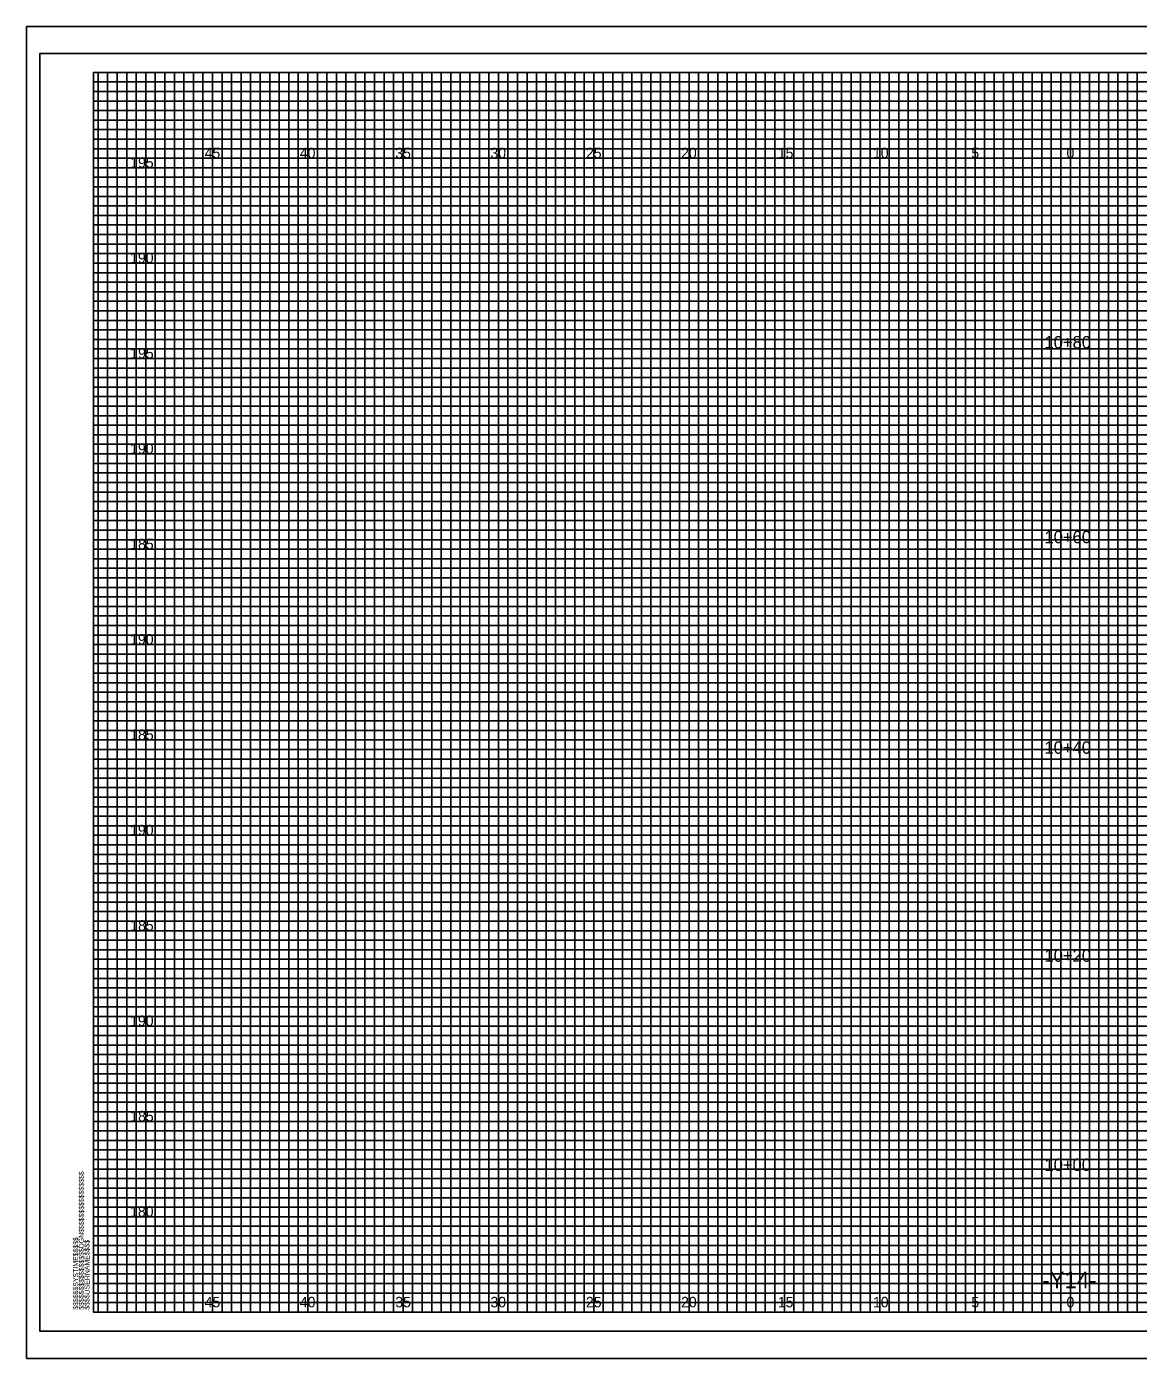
# Model space of a CAD drawing. Extents: x -4 to 103, y -2 to 138.
# Drawn here: x -3.5 to 54.8, y -2.4 to 67.4 of the extents above; entities that cross this region are included whole.
import ezdxf

# ---------------------------------------------------------------- set-up
doc = ezdxf.new("R2010")
doc.units = 0
for name, color, linetype in [('Old_Level_10', 7, 'Continuous'), ('Old_Level_16', 7, 'Continuous'), ('Old_Level_3', 7, 'Continuous'), ('Old_Level_5', 7, 'Continuous'), ('Old_Level_8', 7, 'Continuous'), ('Prop Dimension', 7, 'Continuous'), ('Prop XS Finish Grade Earthwork', 7, 'Continuous'), ('Prop XS Pvmt Edge Slope', 7, 'Continuous'), ('Prop XS SE Text', 7, 'Continuous'), ('Prop XS Subgrade Earthwork', 7, 'Continuous'), ('Prop XSC Text', 7, 'Continuous')]:
    doc.layers.add(name, color=color, linetype=linetype)

msp = doc.modelspace()

# ---------------------------------------------------------------- linework, layer by layer
at = {"layer": 'Old_Level_10'}
for p, q in [((1.25, 0), (1.25, 65)), ((3.75, 0), (3.75, 65)), ((6.25, 0), (6.25, 65)), ((8.75, 0), (8.75, 65)), ((11.25, 0), (11.25, 65)), ((13.75, 0), (13.75, 65)), ((16.25, 0), (16.25, 65)), ((18.75, 0), (18.75, 65)), ((21.25, 0), (21.25, 65)), ((23.75, 0), (23.75, 65)), ((26.25, 0), (26.25, 65)), ((28.75, 0), (28.75, 65)), ((31.25, 0), (31.25, 65)), ((33.75, 0), (33.75, 65)), ((36.25, 0), (36.25, 65)), ((38.75, 0), (38.75, 65)), ((41.25, 0), (41.25, 65)), ((43.75, 0), (43.75, 65)), ((46.25, 0), (46.25, 65)), ((48.75, 0), (48.75, 65)), ((51.25, 0), (51.25, 65)), ((53.75, 0), (53.75, 65)), ((0, 62.5), (74.25, 62.5)), ((0, 60), (102.5, 60)), ((0, 57.5), (102.5, 57.5)), ((0, 55), (102.5, 55)), ((0, 52.5), (102.5, 52.5)), ((0, 50), (102.5, 50)), ((0, 47.5), (102.5, 47.5)), ((0, 45), (102.5, 45)), ((0, 42.5), (102.5, 42.5)), ((0, 40), (102.5, 40)), ((0, 37.5), (102.5, 37.5)), ((0, 35), (102.5, 35)), ((0, 32.5), (102.5, 32.5)), ((0, 30), (102.5, 30)), ((0, 27.5), (102.5, 27.5)), ((0, 25), (102.5, 25)), ((0, 22.5), (102.5, 22.5)), ((0, 20), (102.5, 20)), ((0, 17.5), (102.5, 17.5)), ((0, 15), (102.5, 15)), ((0, 12.5), (102.5, 12.5)), ((0, 10), (102.5, 10)), ((0, 7.5), (102.5, 7.5)), ((0, 5), (102.5, 5)), ((0, 2.5), (102.5, 2.5))]:
    msp.add_line(p, q, dxfattribs=at)
at = {"layer": 'Old_Level_3'}
for p, q in [((-3.5, 67.4), (103.4, 67.4)), ((-3.5, 67.4), (-3.5, -2.425)), ((-3.5, -2.425), (103.4, -2.425))]:
    msp.add_line(p, q, dxfattribs=at)
at = {"layer": 'Old_Level_5'}
msp.add_lwpolyline([(103.4, 67.4), (-3.5, 67.4), (-3.5, -2.425), (103.4, -2.425)], close=True, dxfattribs=at)
at = {"layer": 'Old_Level_8'}
for points in [[(1.25, 0), (1.25, 65), (3.75, 65), (3.75, 0), (6.25, 0), (6.25, 65), (8.75, 65), (8.75, 0), (11.25, 0), (11.25, 65), (13.75, 65), (13.75, 0), (16.25, 0), (16.25, 65), (18.75, 65), (18.75, 0), (21.25, 0), (21.25, 65), (23.75, 65), (23.75, 0), (26.25, 0), (26.25, 65), (28.75, 65), (28.75, 0), (31.25, 0), (31.25, 65), (33.75, 65), (33.75, 0), (36.25, 0), (36.25, 65), (38.75, 65), (38.75, 0), (41.25, 0), (41.25, 65), (43.75, 65), (43.75, 0), (46.25, 0), (46.25, 65), (48.75, 65), (48.75, 0), (51.25, 0), (51.25, 65), (53.75, 65), (53.75, 0)], [(102.5, 60), (0, 60), (0, 62.5), (74.25, 62.5)], [(102.5, 55), (0, 55), (0, 57.5), (102.5, 57.5)], [(102.5, 50), (0, 50), (0, 52.5), (102.5, 52.5)], [(102.5, 45), (0, 45), (0, 47.5), (102.5, 47.5)], [(102.5, 40), (0, 40), (0, 42.5), (102.5, 42.5)], [(102.5, 35), (0, 35), (0, 37.5), (102.5, 37.5)], [(102.5, 30), (0, 30), (0, 32.5), (102.5, 32.5)], [(102.5, 25), (0, 25), (0, 27.5), (102.5, 27.5)], [(102.5, 20), (0, 20), (0, 22.5), (102.5, 22.5)], [(102.5, 15), (0, 15), (0, 17.5), (102.5, 17.5)], [(102.5, 10), (0, 10), (0, 12.5), (102.5, 12.5)], [(102.5, 5), (0, 5), (0, 7.5), (102.5, 7.5)], [(0, 2.5), (102.5, 2.5)]]:
    msp.add_lwpolyline(points, dxfattribs=at)
at = {"layer": 'Prop Dimension'}
for points in [[(0.25, 0), (0.25, 65), (0.75, 65), (0.75, 0), (1.75, 0), (1.75, 65), (2.25, 65), (2.25, 0), (2.75, 0), (2.75, 65), (3.25, 65), (3.25, 0), (4.25, 0), (4.25, 65), (4.75, 65), (4.75, 0), (5.25, 0), (5.25, 65), (5.75, 65), (5.75, 0), (6.75, 0), (6.75, 65), (7.25, 65), (7.25, 0), (7.75, 0), (7.75, 65), (8.25, 65), (8.25, 0), (9.25, 0), (9.25, 65), (9.75, 65), (9.75, 0), (10.25, 0), (10.25, 65), (10.75, 65), (10.75, 0), (11.75, 0), (11.75, 65), (12.25, 65), (12.25, 0), (12.75, 0), (12.75, 65), (13.25, 65), (13.25, 0), (14.25, 0), (14.25, 65), (14.75, 65), (14.75, 0), (15.75, 0), (15.25, 0), (15.25, 65), (15.75, 65), (15.75, 0), (16.75, 0), (16.75, 65), (17.25, 65), (17.25, 0), (17.75, 0), (17.75, 65), (18.25, 65), (18.25, 0), (19.25, 0), (19.25, 65), (19.75, 65), (19.75, 0), (20.25, 0), (20.25, 65), (20.75, 65), (20.75, 0), (21.75, 0), (21.75, 65), (22.25, 65), (22.25, 0), (22.75, 0), (22.75, 65), (23.25, 65), (23.25, 0), (24.25, 0), (24.25, 65), (24.75, 65), (24.75, 0), (25.25, 0), (25.25, 65), (25.75, 65), (25.75, 0), (26.75, 0), (26.75, 65), (27.25, 65), (27.25, 0), (27.75, 0), (27.75, 65), (28.25, 65), (28.25, 0), (29.25, 0), (29.25, 65), (29.75, 65), (29.75, 0), (30.25, 0), (30.25, 65), (30.75, 65), (30.75, 0)], [(30.75, 0), (31.75, 0), (31.75, 65), (32.25, 65), (32.25, 0), (32.75, 0), (32.75, 65), (33.25, 65), (33.25, 0), (34.25, 0), (34.25, 65), (34.75, 65), (34.75, 0), (35.25, 0), (35.25, 65), (35.75, 65), (35.75, 0), (36.75, 0), (36.75, 65), (37.25, 65), (37.25, 0), (37.75, 0), (37.75, 65), (37.75, 0)], [(38.25, 65), (38.25, 0), (39.25, 0), (39.25, 65), (39.75, 65), (39.75, 0), (40.25, 0), (40.25, 65), (40.75, 65), (40.75, 0), (41.75, 0), (41.75, 65), (42.25, 65), (42.25, 0), (42.75, 0), (42.75, 65), (43.25, 65), (43.25, 0), (43.75, 0), (44.25, 0), (44.25, 65), (44.75, 65), (44.75, 0), (45.25, 0), (45.25, 65), (45.75, 65), (45.75, 0), (46.75, 0), (46.75, 65), (47.25, 65), (47.25, 0), (47.75, 0), (47.75, 65), (48.25, 65), (48.25, 0), (49.25, 0), (49.25, 65), (49.75, 65), (49.75, 0), (50.25, 0), (50.25, 65), (50.75, 65), (50.75, 0), (51.75, 0), (51.75, 65), (52.25, 65), (52.25, 0), (52.75, 0), (52.75, 65), (53.25, 65), (53.25, 0), (54.25, 0), (54.25, 65), (54.75, 65), (54.75, 0), (55.25, 0)], [(0, 62), (0, 63), (74.25, 63), (74.25, 63.5), (0, 63.5), (0, 64), (74.25, 64), (74.25, 64.5), (0, 64.5)], [(102.5, 62), (0, 62)], [(102.5, 61), (0, 61), (0, 61.5), (102.5, 61.5)], [(102.5, 59.5), (0, 59.5), (0, 60.5), (102.5, 60.5)], [(102.5, 58.5), (0, 58.5), (0, 59), (102.5, 59)], [(102.5, 57), (0, 57), (0, 58), (102.5, 58)], [(102.5, 56), (0, 56), (0, 56.5), (102.5, 56.5)], [(102.5, 54.5), (0, 54.5), (0, 55.5), (102.5, 55.5)], [(102.5, 53.5), (0, 53.5), (0, 54), (102.5, 54)], [(0, 53), (102.5, 53)], [(102.5, 52), (0, 52)], [(102.5, 51), (0, 51), (0, 51.5), (102.5, 51.5)], [(102.5, 49.5), (0, 49.5), (0, 50.5), (102.5, 50.5)], [(102.5, 48.5), (0, 48.5), (0, 49), (102.5, 49)], [(102.5, 47), (0, 47), (0, 48), (102.5, 48)], [(102.5, 46), (0, 46), (0, 46.5), (102.5, 46.5)], [(102.5, 44.5), (0, 44.5), (0, 45.5), (102.5, 45.5)], [(102.5, 43.5), (0, 43.5), (0, 44), (102.5, 44)], [(102.5, 42), (0, 42), (0, 43), (102.5, 43)], [(102.5, 41), (0, 41), (0, 41.5), (102.5, 41.5)], [(102.5, 39.5), (0, 39.5), (0, 40.5), (102.5, 40.5)], [(102.5, 38.5), (0, 38.5), (0, 39), (102.5, 39)], [(102.5, 37), (0, 37), (0, 38), (102.5, 38)], [(102.5, 36), (0, 36), (0, 36.5), (102.5, 36.5)], [(102.5, 34.5), (0, 34.5), (0, 35.5), (102.5, 35.5)], [(102.5, 33.5), (0, 33.5), (0, 34), (102.5, 34)], [(102.5, 32), (0, 32), (0, 33), (102.5, 33)], [(102.5, 31), (0, 31), (0, 31.5)], [(0, 31.5), (102.5, 31.5)], [(102.5, 29.5), (0, 29.5), (0, 30.5), (102.5, 30.5)], [(102.5, 28.5), (0, 28.5), (0, 29), (102.5, 29)], [(102.5, 27), (0, 27), (0, 28), (102.5, 28)], [(102.5, 26), (0, 26), (0, 26.5), (102.5, 26.5)], [(102.5, 24.5), (0, 24.5), (0, 25.5), (102.5, 25.5)], [(102.5, 23.5), (0, 23.5), (0, 24), (102.5, 24)], [(102.5, 22), (0, 22), (0, 23), (102.5, 23)], [(102.5, 21), (0, 21), (0, 21.5), (102.5, 21.5)], [(102.5, 19.5), (0, 19.5), (0, 20.5), (102.5, 20.5)], [(102.5, 18.5), (0, 18.5), (0, 19), (102.5, 19)], [(102.5, 17), (0, 17), (0, 18), (102.5, 18)], [(102.5, 16), (0, 16), (0, 16.5), (102.5, 16.5)], [(102.5, 14.5), (0, 14.5), (0, 15.5), (102.5, 15.5)], [(102.5, 13.5), (0, 13.5), (0, 14), (102.5, 14)], [(102.5, 12), (0, 12), (0, 13), (102.5, 13)], [(102.5, 11), (0, 11), (0, 11.5), (102.5, 11.5)], [(102.5, 9.5), (0, 9.5), (0, 10.5), (102.5, 10.5)], [(102.5, 8.5), (0, 8.5), (0, 9), (102.5, 9)], [(102.5, 7), (0, 7), (0, 8), (102.5, 8)], [(102.5, 6), (0, 6), (0, 6.5), (102.5, 6.5)], [(102.5, 4.5), (0, 4.5), (0, 5.5), (102.5, 5.5)], [(102.5, 3.5), (0, 3.5), (0, 4), (102.5, 4)], [(102.5, 2), (0, 2), (0, 3), (102.5, 3)], [(102.5, 1), (0, 1), (0, 1.5), (102.5, 1.5)], [(0, 0.5), (102.5, 0.5)]]:
    msp.add_lwpolyline(points, dxfattribs=at)
at = {"layer": 'Prop XS SE Text'}
msp.add_lwpolyline([(103, 66), (-2.8, 66), (-2.8, -1), (103, -1)], close=True, dxfattribs=at)
at = {"layer": 'Prop XSC Text'}
msp.add_lwpolyline([(102.5, 65), (0, 65), (0, 0), (102.5, 0)], close=True, dxfattribs=at)

# ---------------------------------------------------------------- texts
at = {"layer": 'Old_Level_16'}
for s, p in [('45', (5.84, 60.5)), ('40', (10.831, 60.5)), ('35', (15.84, 60.5)), ('30', (20.831, 60.5)), ('25', (25.84, 60.5)), ('20', (30.831, 60.5)), ('15', (35.906, 60.5)), ('10', (40.897, 60.5)), ('5', (46.057, 60.5)), ('0', (51.049, 60.5)), ('0', (51.049, 60.5)), ('45', (5.84, 0.25)), ('40', (10.831, 0.25)), ('35', (15.84, 0.25)), ('30', (20.831, 0.25)), ('25', (25.84, 0.25)), ('20', (30.831, 0.25)), ('15', (35.906, 0.25)), ('10', (40.897, 0.25)), ('5', (46.057, 0.25)), ('0', (51.049, 0.25)), ('0', (51.049, 0.25))]:
    msp.add_text(s, height=0.55, dxfattribs=at).set_placement(p)
at = {"layer": 'Old_Level_8'}
msp.add_text('040397', height=0.0025, rotation=90, dxfattribs=at).set_placement((-0.001, 64.986))
at = {"layer": 'Prop XS Finish Grade Earthwork'}
msp.add_text('-Y14-', height=0.875, dxfattribs=at).set_placement((49.773, 1.25))
at = {"layer": 'Prop XS Pvmt Edge Slope'}
for s, p in [('10+80', (49.893, 50.528)), ('10+60', (49.893, 40.313)), ('10+40', (49.893, 29.276)), ('10+20', (49.893, 18.37)), ('10+00', (49.893, 7.403))]:
    msp.add_text(s, height=0.65, dxfattribs=at).set_placement(p)
at = {"layer": 'Prop XS Subgrade Earthwork'}
for s, p in [('195', (1.938, 60)), ('190', (1.93, 55)), ('195', (1.938, 50)), ('190', (1.93, 45)), ('185', (1.938, 40)), ('190', (1.93, 35)), ('185', (1.938, 30)), ('190', (1.93, 25)), ('185', (1.938, 20)), ('190', (1.93, 15)), ('185', (1.938, 10)), ('180', (1.93, 5))]:
    msp.add_text(s, height=0.55, dxfattribs=at).set_placement(p)
at = {"layer": 'Prop XSC Text'}
for s, p in [('$$$$$$$$$$$$$$$$DGN$$$$$$$$$$$$$$$$', (-0.5, 0.125)), ('$$$$$$SYSTIME$$$$$', (-0.797, 0.125)), ('$$$$USERNAME$$$$', (-0.2, 0.125))]:
    msp.add_text(s, height=0.2625, rotation=90, dxfattribs=at).set_placement(p)

doc.saveas('drawing.dxf')
